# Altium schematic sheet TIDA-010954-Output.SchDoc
size 431 x 279 mm; Date: Not shown in title block; ApprovedBy: Not shown in title block; CheckedBy: Not shown in title block; Author: Not shown in title block; CompanyName: Not shown in title block; Engineer: Not shown in title block; Organization: Not shown in title block; Address1: Not shown in title block; Address2: Not shown in title block; Address3: Not shown in title block; Address4: Not shown in title block; DocumentNumber: 2; Revision: Use project parameter SCH_Rev; SheetNumber: 7; SheetTotal: 9; PageSetup: Record=PageOptions¦CenterHorizontal=True¦CenterVertical=True¦PrintScale=1.00¦XCorrection=1.00¦YCorrection=1.00¦PrintKind=0¦BorderSize=5000000¦LeftOffset=0¦BottomOffset=0¦Orientation=2¦PaperLength=1000¦PaperWidth=1000¦Scale=100¦PaperSource=15¦PrintQuality=600¦MediaType=1¦DitherType=10¦PaperKind=Letter¦PrintScaleMode=1
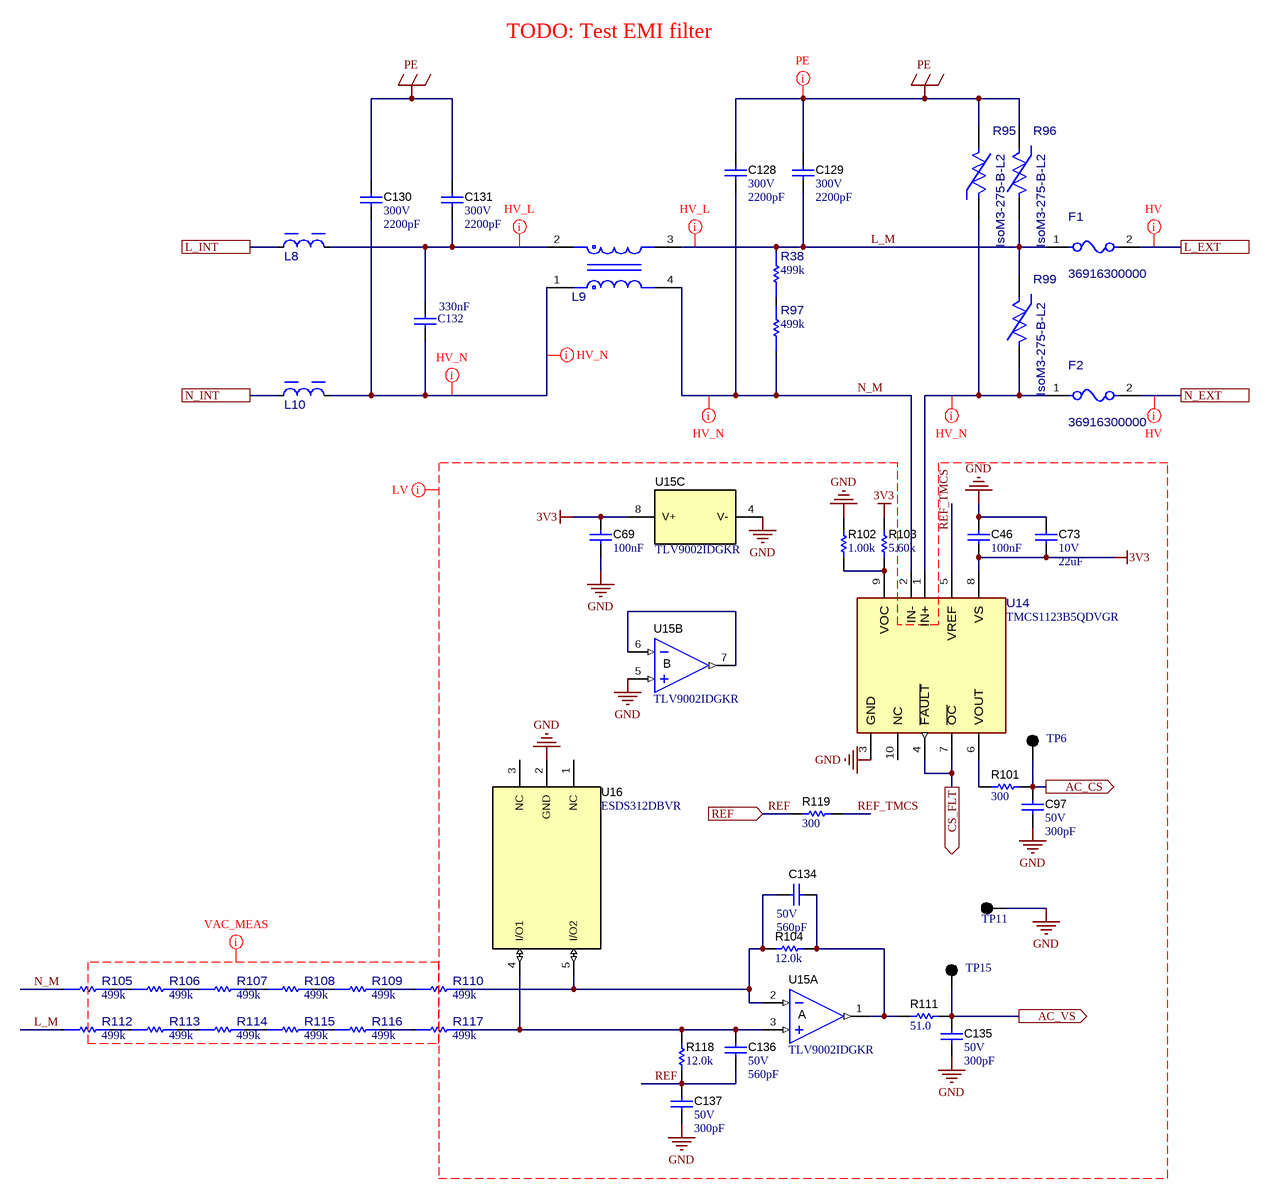
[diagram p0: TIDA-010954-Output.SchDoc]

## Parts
C46  Cap_F: 100nF  [0603]  (hidden comment: CGA3E2X7R1E104K080AA)
C69  Cap_F: 100nF  [0603]  (hidden comment: CGA3E2X7R1E104K080AA)
C73  VDC_V: 10V  ValueDisplayed: 22uF  [1206_180]  (hidden comment: GRM31CR71A226KE15L)
C97  VDC_V: 50V  ValueDisplayed: 300pF  [0603]  (hidden comment: GRM1885C1H301JA01D)
C128  VDC_V: 300V  ValueDisplayed: 2200pF  [E_900x700x900]  (hidden comment: DE6E3KJ222MN3A)
C129  VDC_V: 300V  ValueDisplayed: 2200pF  [E_900x700x900]  (hidden comment: DE6E3KJ222MN3A)
C130  VDC_V: 300V  ValueDisplayed: 2200pF  [E_900x700x900]  (hidden comment: DE6E3KJ222MN3A)
C131  VDC_V: 300V  ValueDisplayed: 2200pF  [E_900x700x900]  (hidden comment: DE6E3KJ222MN3A)
C132  Cap_F: 330nF  [WCAP-FTX2_L18W8.5H14.5_CS]  (hidden comment: 890324025034CS)
C134  VDC_V: 50V  ValueDisplayed: 560pF  [0603]  (hidden comment: GRM1885C1H561JA01D)
C135  VDC_V: 50V  ValueDisplayed: 300pF  [0603]  (hidden comment: GRM1885C1H301JA01D)
C136  VDC_V: 50V  ValueDisplayed: 560pF  [0603]  (hidden comment: GRM1885C1H561JA01D)
C137  VDC_V: 50V  ValueDisplayed: 300pF  [0603]  (hidden comment: GRM1885C1H301JA01D)
F1  36916300000  [FP-36916300000_RADIAL-MFG]
F2  36916300000  [FP-36916300000_RADIAL-MFG]
L8  7443551221  [FP-7443551221_SMD_IND_12MM8_12MM8-MFG]  (value not drawn)
L9  7448025003  [FP-7448025003_PTH_COMMON_CHOKE-MFG]  (value not drawn)
L10  7443551221  [FP-7443551221_SMD_IND_12MM8_12MM8-MFG]  (value not drawn)
R38  value 499k  [FP-ERJP08D4993V_1206-MFG]  (hidden comment: ERJP08D4993V)
R95  IsoM3-275-B-L2  [FP-IsoM3-275-B-L2_RADIAL-MFG]
R96  IsoM3-275-B-L2  [FP-IsoM3-275-B-L2_RADIAL-MFG]
R97  value 499k  [FP-ERJP08D4993V_1206-MFG]  (hidden comment: ERJP08D4993V)
R99  IsoM3-275-B-L2  [FP-IsoM3-275-B-L2_RADIAL-MFG]
R101  ValueDisplayed: 300  [0603]  (hidden comment: RC0603FR-07300RL)
R102  ValueDisplayed: 1.00k  [0603]  (hidden comment: RC0603FR-071KL)
R103  ValueDisplayed: 5.60k  [0603]  (hidden comment: RC0603FR-075K6L)
R104  ValueDisplayed: 12.0k  [0603]  (hidden comment: RT0603BRD0712KL)
R105  value 499k  [FP-ERJP08D4993V_1206-MFG]  (hidden comment: ERJP08D4993V)
R106  value 499k  [FP-ERJP08D4993V_1206-MFG]  (hidden comment: ERJP08D4993V)
R107  value 499k  [FP-ERJP08D4993V_1206-MFG]  (hidden comment: ERJP08D4993V)
R108  value 499k  [FP-ERJP08D4993V_1206-MFG]  (hidden comment: ERJP08D4993V)
R109  value 499k  [FP-ERJP08D4993V_1206-MFG]  (hidden comment: ERJP08D4993V)
R110  value 499k  [FP-ERJP08D4993V_1206-MFG]  (hidden comment: ERJP08D4993V)
R111  ValueDisplayed: 51.0  [0603]  (hidden comment: RC0603FR-0751RL)
R112  value 499k  [FP-ERJP08D4993V_1206-MFG]  (hidden comment: ERJP08D4993V)
R113  value 499k  [FP-ERJP08D4993V_1206-MFG]  (hidden comment: ERJP08D4993V)
R114  value 499k  [FP-ERJP08D4993V_1206-MFG]  (hidden comment: ERJP08D4993V)
R115  value 499k  [FP-ERJP08D4993V_1206-MFG]  (hidden comment: ERJP08D4993V)
R116  value 499k  [FP-ERJP08D4993V_1206-MFG]  (hidden comment: ERJP08D4993V)
R117  value 499k  [FP-ERJP08D4993V_1206-MFG]  (hidden comment: ERJP08D4993V)
R118  ValueDisplayed: 12.0k  [0603]  (hidden comment: RT0603BRD0712KL)
R119  ValueDisplayed: 300  [0603]  (hidden comment: RC0603FR-07300RL)
TP6  5011  [Keystone5011]  (value not drawn)
TP11  5011  [Keystone5011]  (value not drawn)
TP15  5011  [Keystone5011]  (value not drawn)
U14  TMCS1123B5QDVGR  [DVG0010A-MFG]
U15  TLV9002IDGKR  [DGK0008A_N]  (parts A,B,C of 3)
U16  ESDS312DBVR  [DBV0005A_N]

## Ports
AC_CS (out), AC_VS (out), CS_FLT (out), L_EXT, L_INT, N_EXT, N_INT, REF (in)

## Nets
3V3: C46.1 C69.2 C73.2 R103.1 U14.8(VS) U15.8(V+)
GND: C46.2 C69.1 C73.1 C97.2 C135.2 C137.2 R102.1 TP11.1 U14.3(GND) U15.4(V-) U15.5(IN+) U16.2(GND)
PE: C128.2 C129.1 C130.1 C131.2 R95.1 R96.2
AC_CS: C97.1 R101.1 TP6.1 ; port AC_CS
AC_VS: C135.1 R111.2 TP15.1 ; port AC_VS
CS_FLT: U14.4(~{FAULT}) U14.7(~{OC}) ; port CS_FLT
L_EXT: F1.2 ; port L_EXT
L_INT: L8.1 ; port L_INT
L_M: C129.2 F1.1 L9.3 R38.2 R96.1 R99.2 R112.1
N_EXT: F2.2 ; port N_EXT
N_INT: L10.1 ; port N_INT
N_M: C128.1 L9.4 R97.1 R105.1 U14.2(IN-)
REF: C136.2 C137.1 R118.1 R119.2 ; port REF
REF_TMCS: R119.1 U14.5(VREF)
NetC130_2: C130.2 C132.1 L9.1 L10.2
NetC131_1: C131.1 C132.2 L8.2 L9.2
NetC134_1: C134.1 R104.1 R111.1 U15.1(OUT)
NetC134_2: C134.2 R104.2 R110.2 U15.2(IN-) U16.5(I/O2)
NetC136_1: C136.1 R117.2 R118.2 U15.3(IN+) U16.4(I/O1)
NetF2_1: F2.1 R95.2 R99.1 U14.1(IN+)
NetR38_1: R38.1 R97.2
NetR101_2: R101.2 U14.6(VOUT)
NetR102_2: R102.2 R103.2 U14.9(VOC)
NetR105_2: R105.2 R106.1
NetR106_2: R106.2 R107.1
NetR107_2: R107.2 R108.1
NetR108_2: R108.2 R109.1
NetR109_2: R109.2 R110.1
NetR112_2: R112.2 R113.1
NetR113_2: R113.2 R114.1
NetR114_2: R114.2 R115.1
NetR115_2: R115.2 R116.1
NetR116_2: R116.2 R117.1
NetU15_6: U15.6(IN-) U15.7(OUT)

Not connected (* = marked no-connect by the designer): U14 10(NC); U16 1(NC) 3(NC)

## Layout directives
net class HV_N: N_M, NetC130_2, NetF2_1
net class HV_L: L_M, NetC131_1
net class HV: L_EXT, N_EXT
net class PE: PE
net class LV: 3V3, GND, REF, REF_TMCS
net class VAC_MEASURE: (no net found under the mark)

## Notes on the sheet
- TODO: Test EMI filter

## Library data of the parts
C46 C69 = CMP-0007077-5: CAP, CERM, 0.1 uF, 25 V, +/- 10%, X7R, AEC-Q200 Grade 1, 0603; Manufacturer: TDK; TaMin_C: -55°C; Polarized: N; SizeAreaWB_mm2: 4.68; Value1: Unknown; U/M: EA; Value: 0.1uF; TaMax_C: 125°C; SizeZ_mm: 1; SizeX_mm: 1.6; SizeY_mm: 0.8; Value2: 25V; SizeArea_mm2: 1.28; AEC Qualified: Y; AEC Category: Q200
C73 = CMP-0008959-2: CAP, CERM, 22 uF, 10 V, +/- 10%, X7R, 1206; Manufacturer: MuRata; TaMin_C: -55°C; Polarized: N; SizeAreaWB_mm2: 10.92; Value1: Unknown; U/M: EA; Value: 22uF; TaMax_C: 125°C; SizeZ_mm: 1.8; SizeX_mm: 3.2; SizeY_mm: 1.6; Cap_Case: 1206; SizeArea_mm2: 5.12; Cap_F: 22µF; AEC Category: Q200
C97 C135 C137 = CMP-0007206-4: CAP, CERM, 300 pF, 50 V, +/- 5%, C0G/NP0, 0603; Manufacturer: MuRata; TaMin_C: -55°C; Polarized: N; SizeAreaWB_mm2: 4.68; Value1: Unknown; U/M: EA; Value: 300pF; TaMax_C: 125°C; SizeZ_mm: 1; SizeX_mm: 1.6; SizeY_mm: 0.8; SizeArea_mm2: 1.28; AEC Category: Q200
C128-C131 = CMP-0009613-2: CAP, CERM, 2200 pF, 300 V, +/- 20%, E, TH, 2- Leads, Body 9x7mm, Pin Spacing 7.5mm; Manufacturer: MuRata; TaMin_C: -40°C; Polarized: N; SizeAreaWB_mm2: 99; Value1: Unknown; U/M: EA; Value: 2200pF; TaMax_C: 125°C; SizeZ_mm: 12; SizeX_mm: 9; SizeY_mm: 7; Cap_Case: 9x7x9mm; SizeArea_mm2: 63; Cap_F: 2.2nF; AEC Category: Q200
C132 = CMP-0118136-1: WCAP-FTX2 Film Capacitor, THT, L18 x W8.5 x H14.5mm, 330nF, 275V; Manufacturer: Wurth Elektronik; Capacitance Tolerance: +/-10%; Dissipation Factor @100kHz: 2%; Dissipation Factor @10kHz: 0.2%; Dissipation Factor @1kHz: 0.1%; Insulation Resistance: 30000MOhm; Pitch: 15mm; Rate of Voltage Rise: 260V/us; Technical Reference: MX2P015334K275ACPP46004
C134 C136 = CMP-0007225-4: CAP, CERM, 560 pF, 50 V, +/- 5%, C0G/NP0, 0603; Manufacturer: MuRata; TaMin_C: -55°C; Polarized: N; SizeAreaWB_mm2: 4.68; Value1: Unknown; U/M: EA; Value: 560pF; TaMax_C: 125°C; SizeZ_mm: 1; SizeX_mm: 1.6; SizeY_mm: 0.8; SizeArea_mm2: 1.28; AEC Category: Q200
F1 F2 = CMP-0123009-1: 6.3 A 300 V AC DC Fuse Board Mount (Cartridge Style Excluded) Through Hole Radial, Box; Manufacturer: Littelfuse Inc; Interrupt_AC: 50A; MeltingTyp: 160.74A2Sec; SizeZ_mm: 8mm; VAC_V: 300V; Fuse Speed: Slow; AEC Qualified: No; Fuse Current: 6.3A; Fuse Voltage Drop: 65mV; Res_ohm: 0.0077Ω; Standoff Height: 0.5mm
L8 L10 = CMP-0095148-1: 22 µH Shielded Wirewound Inductor 6 A 24.7mOhm Nonstandard; Manufacturer: Wurth Electronics; Self Resonant Frequency: 14MHz; TaMin_C: -40°C; AEC Grade: Grade 1; Irms: 6A; Value: 22uH; DCR_ohm: 27.17m; AEC Qualified: Yes; TaMax_C: +105°C; Test Frequency: 100kHz; Shrouded: true; SizeZ_mm: 6.5mm; Isat: 3A; Ind_H: 22µH; Tolerance_%: 20%
L9 = CMP-0094060-1: 2.5 mH @ 10 kHz 2 Line Common Mode Choke Through Hole 5A DCR 15mOhm; Manufacturer: Wurth Electronics; Ind_H: 2.5mH; DCR_ohm: 15m; SizeZ_mm: 22mm; Tolerance_%: +50/-30%; Test Frequency: 10kHz; AEC Qualified: No
R38 R97 R105-R110 R112-R117 = CMP-0122928-1: 499 kOhms ±0.5% 0.667W, 2/3W Chip Resistor 1206 (3216 Metric) Automotive AEC-Q200, Pulse Withstanding Thick Film; Manufacturer: Panasonic; AEC Grade: Grade 0; AEC Qualified: Yes; Power_W: 660mW; SizeZ_mm: 0.7mm; TempCo: 100ppm/°C; VDC_V: 500V
R95 R96 R99 = CMP-0097027-1: 3 kA Varistor 1 Circuit Through Hole Disc 13.2mm; Manufacturer: Bourns; VDC_V: 350V; Vc: 50A; Cap_F: 30pF; AEC Qualified: No; Clamping Voltage: 730V; SizeZ_mm: 19mm
R101 R119 = CMP-0023013-5: RES, 300, 1%, 0.1 W, 0603; Manufacturer: Yageo; Power_W: 100mW; TempCo: 100 ppm/C; Value_Code: 300R; Value: 300; SizeX_mm: 1.6; SizeY_mm: 0.8; SizeZ_mm: 1; Value2: 0.1W; SizeArea_mm2: 1.28; AEC Qualified: N; VDC_V: 75V; AEC Category: Q200; SizeAreaWB_mm2: 4.68
R102 = CMP-0022895-5: RES, 1.00 k, 1%, 0.1 W, 0603; Manufacturer: Yageo; Power_W: 100mW; TempCo: 100 ppm/C; Value_Code: 1k00; Value: 1.00k; EIA_Code: E96; Res_ohm: 1k; SizeX_mm: 1.6; SizeY_mm: 0.8; SizeZ_mm: 1; Value2: 0.1W; SizeArea_mm2: 1.28; AEC Qualified: N; VDC_V: 75V; AEC Category: Q200; SizeAreaWB_mm2: 4.68
R103 = CMP-0023203-5: RES, 5.60 k, 1%, 0.1 W, 0603; Manufacturer: Yageo; Power_W: 100mW; TempCo: 100 ppm/C; Value_Code: 5k60; Value: 5.60k; Res_ohm: 5.6k; SizeX_mm: 1.6; SizeY_mm: 0.8; SizeZ_mm: 1; Value2: 0.1W; SizeArea_mm2: 1.28; AEC Qualified: N; VDC_V: 75V; AEC Category: Q200; SizeAreaWB_mm2: 4.68
R104 R118 = CMP-0023710-3: RES, 12.0 k, 0.1%, 0.1 W, 0603; Manufacturer: Yageo America; Power_W: 100mW; TempCo: 25 ppm/C; Value_Code: 12k0; U/M: EA; Value: 12.0k; EIA_Code: E192; Res_ohm: 12k; SizeX_mm: 1.6; SizeY_mm: 0.8; SizeZ_mm: 1; Value2: 0.1W; SizeArea_mm2: 1.28; VDC_V: 75V; AEC Category: Q200
R111 = CMP-0023169-5: RES, 51.0, 1%, 0.1 W, 0603; Manufacturer: Yageo; Power_W: 100mW; TempCo: 100 ppm/C; Value_Code: 51R0; Value: 51.0; Res_ohm: 51; SizeX_mm: 1.6; SizeY_mm: 0.8; SizeZ_mm: 1; Value2: 0.1W; SizeArea_mm2: 1.28; AEC Qualified: N; VDC_V: 75V; AEC Category: Q200; SizeAreaWB_mm2: 4.68
TP6 TP11 TP15 = CMP-0055148-2: Test Point, Multipurpose, Black, TH; Manufacturer: Keystone Electronics; CNHeader: FALSE; ContactFinish: Silver; Green_REACh: Passed; Green_Lifecycle: Active; CT: TRUE
U14 = CMP-0096055-1: Manufacturer: Texas Instruments; Standoff Height: 0.1mm; SizeZ_mm: 2.65mm
U15 = CMP-0073533-3: 350 kHz, Low-Noise, RRIO, CMOS Operational Amplifier for Cost-Sensitive Systems, DGK0008A (VSSOP-8); Alternate PartNumber: TLV2333IDGKT; Alternate Manufacturer: Texas Instruments; SizeAreaWB_mm2: 23.6; SizeZ_mm: 1.1; SizeX_mm: 4.9; SizeY_mm: 3; SizeArea_mm2: 14.7; CompType: IC; AEC Category: Q200; AEC Qualified: N
U16 = CMP-0085634-1: 3.6V Data-Line Surge and 30kV ESD Protection Diode Array, DBV0005A (SOT-23-5); Alternate Manufacturer: Texas Instruments; SizeX_mm: 2.8; SizeArea_mm2: 8.12; Rating: Catalog; SizeAreaWB_mm2: 14.82; AEC Category: Q200; AEC Qualified: N; CompType: IC; SizeZ_mm: 1.45; SizeY_mm: 2.9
